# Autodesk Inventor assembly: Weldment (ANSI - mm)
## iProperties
Length Units: 11269
Angle Units: 11283
Time Units: 11279
Mass Units: 11290
Length Display Precision: 3
Angle Display Precision: 2
Part Number: Weldment (ANSI - mm)
Document SubType Name: Weldment
Created: 2002-06
Designer: smithga
Part Number: Tutorial1
Created: 2003-01
Designer: Owner
Control State: 0
Master: False
Shininess: 64.0
Angle Units: 11279
Time Units: 11290
Mass Units: 11283
Compacted: True
Density: 0.0
Volumn: 0.0
Area: 0.0
PropertySet Name: Model Information
Author: Owner
